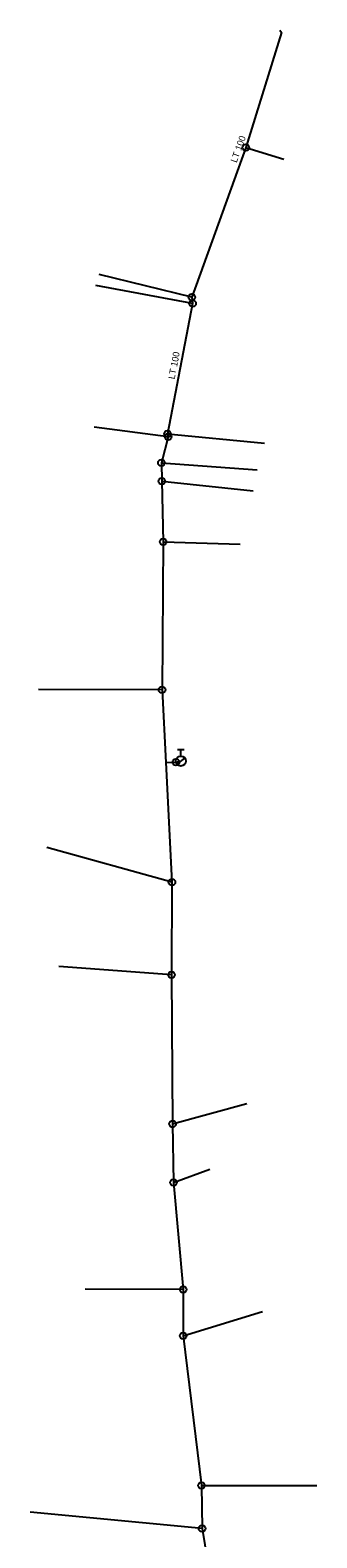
# Model space of a CAD drawing. Extents: x -684724 to -684366, y -1163865 to -1163489.
# Drawn here: x -684474.8 to -684453.1, y -1163602.4 to -1163488.7 of the extents above; entities that cross this region are included whole.
import ezdxf

# ---------------------------------------------------------------- set-up
doc = ezdxf.new("R2010")
doc.units = 0
for name, color, linetype in [('Hydranty', 7, 'Continuous'), ('Popis vodovodních řadů', 7, 'Continuous'), ('Vod přípojky-voda pitná', 7, 'Continuous'), ('Vodovodní řad', 7, 'Continuous'), ('Vodovodní šoupata', 7, 'Continuous')]:
    doc.layers.add(name, color=color, linetype=linetype)

msp = doc.modelspace()

# ---------------------------------------------------------------- linework, layer by layer
at = {"layer": 'Hydranty'}
for p, q in [((-684463.7, -1163544.06), (-684463.11, -1163543.6)), ((-684463.66, -1163542.95), (-684463.16, -1163542.95)), ((-684463.41, -1163543.45), (-684463.41, -1163542.95))]:
    msp.add_line(p, q, dxfattribs=at)
msp.add_circle((-684463.41, -1163543.83), 0.375, dxfattribs=at)
at = {"layer": 'Vod přípojky-voda pitná'}
for points in [[(-684458.5, -1163497.58), (-684455.64, -1163498.46)], [(-684462.58, -1163508.87), (-684469.58, -1163507.15)], [(-684462.52, -1163509.34), (-684469.84, -1163507.99)], [(-684464.36, -1163519.4), (-684469.96, -1163518.67)], [(-684464.41, -1163519.17), (-684457.1, -1163519.88)], [(-684464.88, -1163521.35), (-684457.64, -1163521.89)], [(-684464.85, -1163522.74), (-684457.95, -1163523.47)], [(-684464.75, -1163527.3), (-684458.94, -1163527.47)], [(-684464.83, -1163538.46), (-684474.16, -1163538.43)], [(-684464.08, -1163552.95), (-684473.52, -1163550.34)], [(-684464.11, -1163559.94), (-684472.61, -1163559.31)], [(-684464.03, -1163571.18), (-684458.44, -1163569.65)], [(-684463.97, -1163575.6), (-684461.22, -1163574.6)], [(-684463.24, -1163583.66), (-684470.64, -1163583.64)], [(-684463.24, -1163587.15), (-684457.24, -1163585.31)], [(-684461.85, -1163598.43), (-684453.14, -1163598.44)], [(-684461.81, -1163601.67), (-684474.79, -1163600.45)]]:
    msp.add_lwpolyline(points, dxfattribs=at)
at = {"layer": 'Vodovodní řad'}
for points in [[(-684455.93, -1163488.74), (-684455.8, -1163488.91), (-684458.5, -1163497.58), (-684462.58, -1163508.87)], [(-684462.58, -1163508.87), (-684462.52, -1163509.34), (-684464.41, -1163519.17), (-684464.36, -1163519.4), (-684464.88, -1163521.35)], [(-684464.88, -1163521.35), (-684464.85, -1163522.74), (-684464.75, -1163527.3), (-684464.83, -1163538.46), (-684464.55, -1163543.94), (-684464.08, -1163552.95), (-684464.11, -1163559.94), (-684464.03, -1163571.18), (-684463.97, -1163575.6), (-684463.24, -1163583.66), (-684463.24, -1163587.15), (-684461.85, -1163598.43), (-684461.81, -1163601.67), (-684460.58, -1163609.2), (-684460.2, -1163612.15)], [(-684464.55, -1163543.94), (-684463.78, -1163543.91), (-684463.41, -1163543.83)]]:
    msp.add_lwpolyline(points, dxfattribs=at)
at = {"layer": 'Vodovodní šoupata'}
for centre in [(-684458.5, -1163497.58), (-684462.58, -1163508.87), (-684462.52, -1163509.34), (-684464.41, -1163519.17), (-684464.36, -1163519.4), (-684464.88, -1163521.35), (-684464.85, -1163522.74), (-684464.75, -1163527.3), (-684464.83, -1163538.46), (-684463.78, -1163543.91), (-684464.08, -1163552.95), (-684464.11, -1163559.94), (-684464.03, -1163571.18), (-684463.97, -1163575.6), (-684463.24, -1163583.66), (-684463.24, -1163587.15), (-684461.85, -1163598.43), (-684461.81, -1163601.67)]:
    msp.add_circle(centre, 0.25, dxfattribs=at)

# ---------------------------------------------------------------- texts
at = {"layer": 'Popis vodovodních řadů'}
for rotation, p in [(70.1311, (-684459.2, -1163498.77)), (79.1166, (-684463.88, -1163515.08))]:
    msp.add_text('LT 100', height=0.5, rotation=rotation, dxfattribs=at).set_placement(p)

doc.saveas('drawing.dxf')
